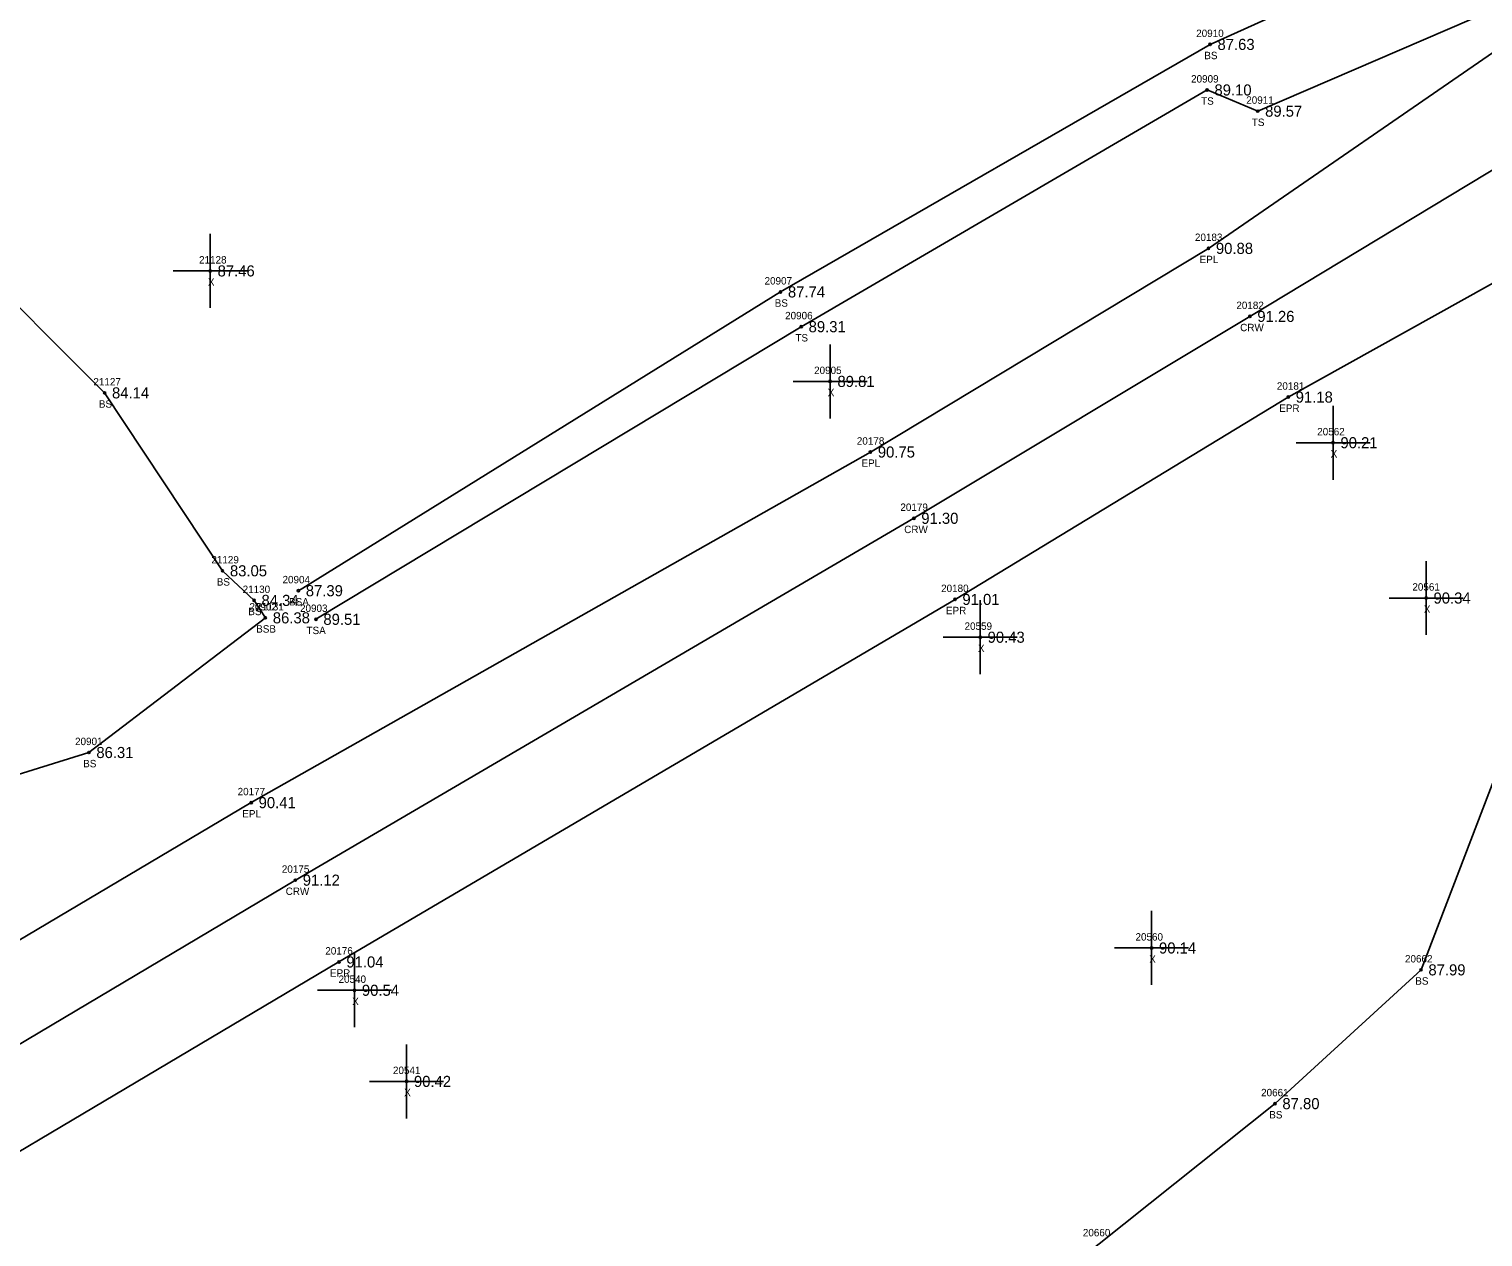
# Model space of a CAD drawing. Extents: x 2530197 to 2532051, y 935230 to 936631.
# Drawn here: x 2531512.9 to 2531709.5, y 936164.7 to 936328 of the extents above; entities that cross this region are included whole.
import ezdxf

# ---------------------------------------------------------------- set-up
doc = ezdxf.new("R2010")
doc.units = 0
for name, color, linetype in [('RD_DTM_BkLn1', 7, 'Continuous'), ('RD_DTM_BkLn2', 7, 'Continuous'), ('RD_DTM_BkLn_txCode', 7, 'Continuous'), ('RD_EX_Misc', 7, 'Continuous'), ('RD_EX_Misc_txCode', 7, 'Continuous'), ('RD_EX_Road', 7, 'Continuous'), ('RD_EX_Road_txCode', 7, 'Continuous'), ('RD_EX_TX_Misc_ELEV', 7, 'Continuous'), ('RD_EX_TX_Road_ELEV', 7, 'Continuous'), ('RD_HC_Survey_ELEV', 7, 'Continuous'), ('RD_HC_Survey_txCode', 7, 'Continuous'), ('RD_SMD_Locator', 7, 'Continuous')]:
    doc.layers.add(name, color=color, linetype=linetype)

msp = doc.modelspace()

# ---------------------------------------------------------------- linework, layer by layer
at = {"layer": 'RD_DTM_BkLn1'}
msp.add_lwpolyline([(2531175.16, 935992.09), (2531214.08, 936014.93), (2531297.2, 936064.16), (2531382.2, 936114.3), (2531466.12, 936163.77), (2531548.89, 936212.96), (2531632.55, 936261.89), (2531678, 936289.19), (2531722.34, 936315.93), (2531754.26, 936342.49), (2531759.78, 936349.83), (2531772.77, 936373.29), (2531778.96, 936389.71), (2531793.78, 936438.29), (2531813.65, 936511.36), (2531832.39, 936582.88)], dxfattribs=at)
at = {"layer": 'RD_DTM_BkLn2'}
for points in [[(2531549.3, 936252.1), (2531614.51, 936292.5), (2531672.61, 936325.97), (2531704.5, 936340.37), (2531736.9, 936360.37)], [(2531551.68, 936248.23), (2531617.31, 936287.8), (2531672.2, 936319.81), (2531679.05, 936316.94), (2531711.2, 936330.77), (2531738.76, 936358.87)], [(2531493.53, 936221.7), (2531484.53, 936232.43), (2531469.86, 936256.85), (2531452.26, 936270.26), (2531504.04, 936297.86), (2531523.09, 936278.85), (2531539.04, 936254.79), (2531543.31, 936250.79), (2531544.84, 936248.43)], [(2531493.53, 936221.7), (2531520.97, 936230.22), (2531544.84, 936248.43)], [(2531639.71, 936103.64), (2531636.09, 936114.4), (2531633.08, 936120.69), (2531636.02, 936136.76), (2531638.72, 936149.35), (2531657.6, 936163.8), (2531681.39, 936182.74), (2531701.14, 936200.83), (2531713.8, 936233.77)]]:
    msp.add_lwpolyline(points, dxfattribs=at)
at = {"layer": 'RD_EX_Misc'}
for p, q in [((2531537.37, 936290.34), (2531537.37, 936300.34)), ((2531532.37, 936295.34), (2531542.37, 936295.34)), ((2531621.21, 936275.4), (2531621.21, 936285.4)), ((2531616.21, 936280.4), (2531626.21, 936280.4)), ((2531689.24, 936267.11), (2531689.24, 936277.11)), ((2531684.24, 936272.11), (2531694.24, 936272.11)), ((2531701.83, 936246.11), (2531701.83, 936256.11)), ((2531641.52, 936240.81), (2531641.52, 936250.81)), ((2531696.83, 936251.11), (2531706.83, 936251.11)), ((2531636.52, 936245.81), (2531646.52, 936245.81)), ((2531664.7, 936198.79), (2531664.7, 936208.79)), ((2531556.89, 936193.07), (2531556.89, 936203.07)), ((2531659.7, 936203.79), (2531669.7, 936203.79)), ((2531551.89, 936198.07), (2531561.89, 936198.07)), ((2531563.93, 936180.75), (2531563.93, 936190.75)), ((2531558.93, 936185.75), (2531568.93, 936185.75))]:
    msp.add_line(p, q, dxfattribs=at)
at = {"layer": 'RD_EX_Road'}
for points in [[(2531169.65, 936000.77), (2531208.79, 936024.95), (2531292.04, 936074.02), (2531376.24, 936123.7), (2531460.37, 936174.49), (2531542.92, 936223.44), (2531626.67, 936270.85), (2531672.4, 936298.39), (2531714.28, 936327.21), (2531747.19, 936360.45), (2531761.42, 936377.32), (2531773.11, 936411.11), (2531782.2, 936441.65), (2531803.17, 936514.76), (2531820.28, 936585.8)], [(2531180.82, 935982), (2531220.82, 936004.21), (2531303.54, 936053.39), (2531388.75, 936103.71), (2531472.27, 936152.98), (2531554.79, 936201.9), (2531638.11, 936250.92), (2531683.19, 936278.28), (2531730.37, 936304.55), (2531771.5, 936341.26), (2531788.67, 936375.53), (2531805.57, 936434.84), (2531825.53, 936508.74), (2531844.13, 936579.65)]]:
    msp.add_lwpolyline(points, dxfattribs=at)
at = {"layer": 'RD_SMD_Locator'}
for centre in [(2531672.61, 936325.97), (2531672.2, 936319.81), (2531679.05, 936316.94), (2531672.4, 936298.39), (2531537.37, 936295.34), (2531614.51, 936292.5), (2531678, 936289.19), (2531617.31, 936287.8), (2531621.21, 936280.4), (2531523.09, 936278.85), (2531683.19, 936278.28), (2531689.24, 936272.11), (2531626.67, 936270.85), (2531632.55, 936261.89), (2531539.04, 936254.79), (2531549.3, 936252.1), (2531543.31, 936250.79), (2531638.11, 936250.92), (2531701.83, 936251.11), (2531544.84, 936248.43), (2531544.84, 936248.43), (2531551.68, 936248.23), (2531641.52, 936245.81), (2531520.97, 936230.22), (2531542.92, 936223.44), (2531548.89, 936212.96), (2531664.7, 936203.79), (2531554.79, 936201.9), (2531701.14, 936200.83), (2531556.89, 936198.07), (2531563.93, 936185.75), (2531681.39, 936182.74)]:
    msp.add_circle(centre, 0.15, dxfattribs=at)

# ---------------------------------------------------------------- texts
at = {"layer": 'RD_DTM_BkLn_txCode'}
for s, p in [('20910', (2531670.73, 936326.97)), ('BS', (2531671.83, 936323.97)), ('20909', (2531670.04, 936320.81)), ('TS', (2531671.4, 936317.81)), ('20911', (2531677.5, 936317.94)), ('TS', (2531678.26, 936314.94)), ('20907', (2531612.35, 936293.5)), ('BS', (2531613.73, 936290.5)), ('20906', (2531615.13, 936288.8)), ('TS', (2531616.52, 936285.8)), ('21127', (2531521.57, 936279.85)), ('BS', (2531522.31, 936276.85)), ('21129', (2531537.53, 936255.79)), ('20904', (2531547.15, 936253.1)), ('BS', (2531538.26, 936252.79)), ('21130', (2531541.76, 936251.79)), ('20902', (2531542.68, 936249.43)), ('21131', (2531543.61, 936249.43)), ('BSA', (2531548.04, 936250.1)), ('20903', (2531549.52, 936249.23)), ('BS', (2531542.53, 936248.79)), ('BSB', (2531543.59, 936246.43)), ('BSB', (2531543.59, 936246.43)), ('TSA', (2531550.4, 936246.23)), ('20901', (2531519.09, 936231.22)), ('BS', (2531520.19, 936228.22)), ('20662', (2531698.97, 936201.83)), ('BS', (2531700.36, 936198.83)), ('20661', (2531679.51, 936183.74)), ('BS', (2531680.61, 936180.74)), ('20660', (2531655.4, 936164.8))]:
    msp.add_text(s, height=1, dxfattribs=at).set_placement(p)
at = {"layer": 'RD_EX_Misc_txCode'}
for s, p in [('21128', (2531535.86, 936296.34)), ('X', (2531537.06, 936293.34)), ('20905', (2531619.05, 936281.4)), ('X', (2531620.89, 936278.4)), ('20562', (2531687.1, 936273.11)), ('X', (2531688.92, 936270.11)), ('20561', (2531699.97, 936252.11)), ('X', (2531701.52, 936249.11)), ('20559', (2531639.4, 936246.81)), ('X', (2531641.21, 936243.81)), ('20560', (2531662.52, 936204.79)), ('X', (2531664.38, 936201.79)), ('20540', (2531554.73, 936199.07)), ('X', (2531556.58, 936196.07)), ('20541', (2531562.09, 936186.75)), ('X', (2531563.61, 936183.75))]:
    msp.add_text(s, height=1, dxfattribs=at).set_placement(p)
at = {"layer": 'RD_EX_Road_txCode'}
for s, p in [('20183', (2531670.56, 936299.39)), ('EPL', (2531671.19, 936296.39)), ('20181', (2531681.64, 936279.28)), ('EPR', (2531681.96, 936276.28)), ('20178', (2531624.83, 936271.85)), ('EPL', (2531625.46, 936268.85)), ('20180', (2531636.23, 936251.92)), ('EPR', (2531636.88, 936248.92)), ('20177', (2531541.08, 936224.44)), ('EPL', (2531541.71, 936221.44)), ('20176', (2531552.94, 936202.9)), ('EPR', (2531553.57, 936199.9))]:
    msp.add_text(s, height=1, dxfattribs=at).set_placement(p)
at = {"layer": 'RD_EX_TX_Misc_ELEV'}
for s, p in [('87.63', (2531673.61, 936325.22)), ('89.10', (2531673.2, 936319.06)), ('89.57', (2531680.05, 936316.19)), ('87.46', (2531538.37, 936294.59)), ('87.74', (2531615.51, 936291.75)), ('89.31', (2531618.31, 936287.05)), ('84.14', (2531524.09, 936278.1)), ('89.81', (2531622.21, 936279.65)), ('90.21', (2531690.24, 936271.36)), ('83.05', (2531540.04, 936254.04)), ('87.39', (2531550.3, 936251.35)), ('84.34', (2531544.31, 936250.04)), ('90.34', (2531702.83, 936250.36)), ('86.38', (2531545.84, 936247.68)), ('86.38', (2531545.84, 936247.68)), ('89.51', (2531552.68, 936247.48)), ('90.43', (2531642.52, 936245.06)), ('86.31', (2531521.97, 936229.47)), ('90.14', (2531665.7, 936203.04)), ('87.99', (2531702.14, 936200.08)), ('90.54', (2531557.89, 936197.32)), ('90.42', (2531564.93, 936185)), ('87.80', (2531682.39, 936181.99))]:
    msp.add_text(s, height=1.5, dxfattribs=at).set_placement(p)
at = {"layer": 'RD_EX_TX_Road_ELEV'}
for s, p in [('90.88', (2531673.4, 936297.64)), ('91.18', (2531684.19, 936277.53)), ('90.75', (2531627.67, 936270.1)), ('91.01', (2531639.11, 936250.17)), ('90.41', (2531543.92, 936222.69)), ('91.04', (2531555.79, 936201.15))]:
    msp.add_text(s, height=1.5, dxfattribs=at).set_placement(p)
at = {"layer": 'RD_HC_Survey_ELEV'}
for s, p in [('91.26', (2531679, 936288.44)), ('91.30', (2531633.55, 936261.14)), ('91.12', (2531549.89, 936212.21))]:
    msp.add_text(s, height=1.5, dxfattribs=at).set_placement(p)
at = {"layer": 'RD_HC_Survey_txCode'}
for s, p in [('20182', (2531676.16, 936290.19)), ('CRW', (2531676.68, 936287.19)), ('20179', (2531630.72, 936262.89)), ('CRW', (2531631.24, 936259.89)), ('20175', (2531547.06, 936213.96)), ('CRW', (2531547.58, 936210.96))]:
    msp.add_text(s, height=1, dxfattribs=at).set_placement(p)

doc.saveas('drawing.dxf')
